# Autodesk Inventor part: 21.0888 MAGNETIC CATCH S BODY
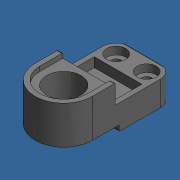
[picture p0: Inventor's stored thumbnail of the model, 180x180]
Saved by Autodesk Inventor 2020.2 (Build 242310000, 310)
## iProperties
Part Number: 21.0888 MAGNETIC CATCH S BODY
Material: ABS Plastic
Document SubType Name: Modeling
Designer: amoles
Appearance: Smooth - White
Mass: 15.3388 g
Surface Area: 80.8674 cm^2
Volume: 14.4705 cm^3
Density: 1.06 g/cm^3
Author: amoles
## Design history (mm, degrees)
feature "Base1"
body "Solid1"
